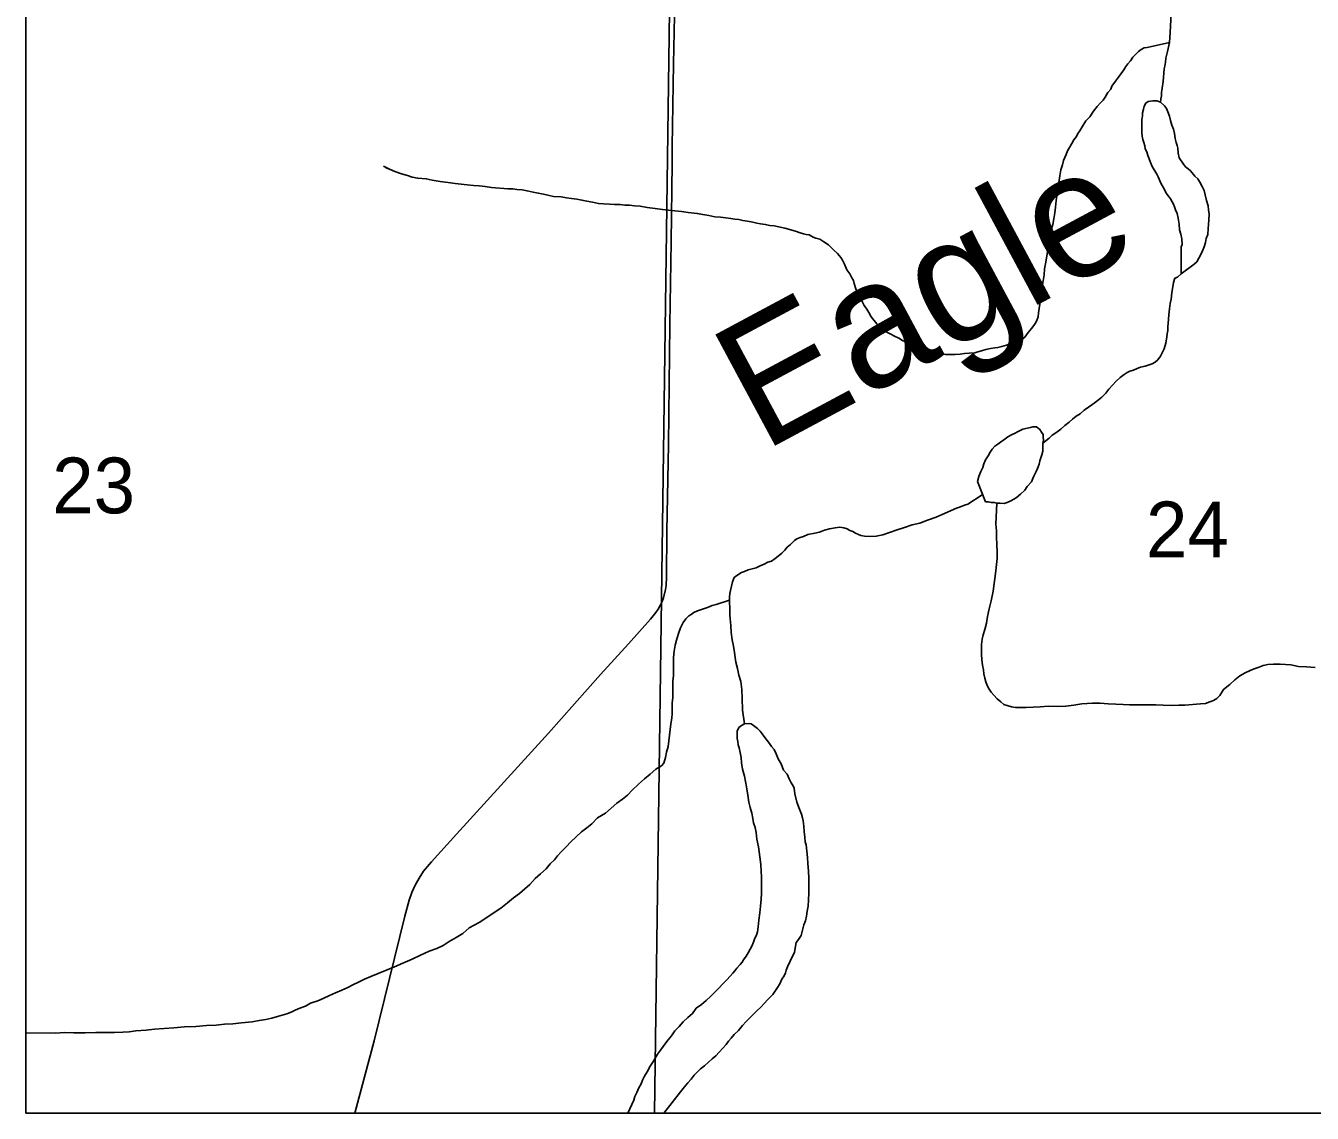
# Model space of a CAD drawing. Extents: x 0 to 68, y 0 to 52.9.
# Drawn here: x 42.258 to 43.278, y 31.143 to 32.005 of the extents above; entities that cross this region are included whole.
import ezdxf

# ---------------------------------------------------------------- set-up
doc = ezdxf.new("R2010")
doc.units = 0
for name, color, linetype in [('Default', 7, 'Continuous'), ('GM_X_Minor_River', 7, 'Continuous'), ('GM_X_Minor_River_Text', 7, 'Continuous'), ('GM_X_Township_Road', 7, 'Continuous')]:
    doc.layers.add(name, color=color, linetype=linetype)

msp = doc.modelspace()

# ---------------------------------------------------------------- linework, layer by layer
at = {"layer": 'Default'}
for q in [(42.2581, 38.5351), (49.6501, 31.1431)]:
    msp.add_line((42.2581, 31.1431), q, dxfattribs=at)
msp.add_lwpolyline([(42.2581, 32.1845), (42.7704, 32.1726), (42.7565, 31.1431)], dxfattribs=at)
at = {"layer": 'GM_X_Minor_River'}
for points in [[(43.1669, 32.0405), (43.1662, 32.0244), (43.1661, 32.0192), (43.1657, 32.0136), (43.1656, 32.0096), (43.1652, 32.0052), (43.1651, 31.9999), (43.1646, 31.9919), (43.163, 31.9847), (43.1617, 31.9795), (43.1613, 31.9763), (43.1608, 31.9731), (43.1604, 31.9711), (43.1595, 31.961), (43.1587, 31.9558), (43.1582, 31.9522), (43.1582, 31.9498), (43.1578, 31.9474), (43.1578, 31.947), (43.1573, 31.9446)], [(42.9282, 31.7746), (42.9325, 31.7689), (42.9365, 31.7648), (42.9405, 31.7624), (42.9437, 31.7607), (42.9465, 31.7591), (42.9501, 31.7575), (42.9529, 31.7558), (42.9553, 31.7546), (42.9581, 31.7526), (42.9617, 31.7505), (42.9653, 31.7493), (42.9677, 31.748), (42.9761, 31.7455), (42.9793, 31.7451), (42.9833, 31.7451), (42.9869, 31.7446), (42.9906, 31.7446), (42.9946, 31.7445), (42.9986, 31.7449), (43.0022, 31.7453), (43.0058, 31.7456), (43.0103, 31.746), (43.0127, 31.7468), (43.0155, 31.7475), (43.0191, 31.7487), (43.0228, 31.7495), (43.026, 31.7498), (43.0284, 31.7502), (43.0316, 31.751), (43.0353, 31.7521), (43.0393, 31.7537), (43.0429, 31.7549), (43.0457, 31.7561), (43.0478, 31.7568), (43.0498, 31.7584), (43.0526, 31.762), (43.0551, 31.7652), (43.0571, 31.7676), (43.0587, 31.77), (43.0596, 31.7724), (43.0604, 31.7744), (43.0608, 31.7776), (43.0617, 31.7844), (43.0626, 31.79), (43.0634, 31.7969), (43.0643, 31.8029), (43.0651, 31.8077), (43.0656, 31.8125), (43.0665, 31.8177), (43.0673, 31.8229), (43.0682, 31.8274), (43.069, 31.8318), (43.0699, 31.8366), (43.0707, 31.8434), (43.072, 31.8478), (43.0728, 31.8522), (43.0737, 31.857), (43.0741, 31.8614), (43.0746, 31.8667), (43.0754, 31.8719), (43.0776, 31.8863), (43.0784, 31.8911), (43.0797, 31.8951), (43.0805, 31.8984), (43.0817, 31.9008), (43.0826, 31.9032), (43.0838, 31.906), (43.0854, 31.9088), (43.0871, 31.9119), (43.0887, 31.9147), (43.0908, 31.9175), (43.092, 31.9199), (43.0936, 31.9219), (43.0952, 31.9251), (43.0981, 31.9299), (43.1014, 31.9331), (43.1042, 31.9375), (43.1071, 31.9411), (43.1095, 31.9439), (43.1119, 31.9462), (43.1136, 31.9486), (43.1156, 31.9522), (43.1181, 31.955), (43.1189, 31.9574), (43.1217, 31.9614), (43.1242, 31.9646), (43.1262, 31.9674), (43.1283, 31.9702), (43.1299, 31.973), (43.1315, 31.975), (43.1335, 31.9774), (43.1356, 31.9802), (43.138, 31.9829), (43.1401, 31.9849), (43.1421, 31.9865), (43.1445, 31.9877), (43.1469, 31.9881), (43.1646, 31.9919)], [(43.1513, 31.9458), (43.1477, 31.9451), (43.1457, 31.9439), (43.1444, 31.9415), (43.144, 31.9391), (43.1432, 31.9363), (43.1432, 31.9339), (43.1427, 31.9307), (43.1427, 31.927), (43.1427, 31.9242), (43.1426, 31.9206), (43.143, 31.9178), (43.1434, 31.915), (43.1442, 31.9126), (43.1449, 31.9101), (43.1453, 31.9077), (43.1465, 31.9053), (43.1473, 31.9025), (43.1485, 31.8997), (43.1496, 31.8968), (43.1508, 31.8936), (43.1544, 31.8875), (43.1556, 31.8855), (43.1563, 31.8835), (43.1575, 31.8811), (43.1587, 31.8786), (43.1607, 31.8754), (43.1619, 31.8726), (43.1638, 31.8702), (43.1654, 31.8681), (43.1666, 31.8657), (43.1678, 31.8637), (43.1686, 31.8617), (43.1694, 31.8592), (43.1705, 31.8564), (43.1713, 31.8528), (43.1721, 31.848), (43.1724, 31.8435), (43.1736, 31.8399), (43.1744, 31.8363), (43.1747, 31.8319), (43.1739, 31.8299), (43.1737, 31.8086)], [(43.1737, 31.8086), (43.1842, 31.8161), (43.1862, 31.8181), (43.1879, 31.8209), (43.1899, 31.8249), (43.1907, 31.8269), (43.192, 31.8301), (43.1932, 31.8333), (43.1937, 31.8365), (43.1949, 31.8397), (43.1953, 31.8445), (43.1954, 31.8477), (43.1958, 31.8513), (43.1959, 31.8558), (43.1955, 31.8594), (43.1951, 31.8626), (43.1939, 31.8666), (43.1928, 31.8711), (43.192, 31.8747), (43.1904, 31.8779), (43.1885, 31.8812), (43.1869, 31.884), (43.1845, 31.886), (43.1813, 31.8901), (43.1793, 31.8917), (43.1773, 31.8933), (43.1757, 31.8954), (43.1722, 31.9006), (43.1714, 31.9042), (43.1711, 31.9083), (43.1707, 31.9103), (43.1699, 31.9127), (43.1691, 31.9159), (43.1684, 31.9199), (43.1676, 31.9232), (43.1664, 31.9264), (43.1652, 31.93), (43.1645, 31.9336), (43.1633, 31.9369), (43.1621, 31.9397), (43.1605, 31.9417), (43.1573, 31.9446), (43.1545, 31.9458), (43.1513, 31.9458)], [(42.5415, 31.8939), (42.5463, 31.8915), (42.5435, 31.8927), (42.5463, 31.8915), (42.5507, 31.8898), (42.5559, 31.8878), (42.5607, 31.8865), (42.5643, 31.8853), (42.5687, 31.8844), (42.5755, 31.8839), (42.5803, 31.8827), (42.5864, 31.8818), (42.5928, 31.8809), (42.5984, 31.8801), (42.6032, 31.8796), (42.608, 31.8792), (42.6129, 31.8787), (42.6173, 31.8783), (42.6221, 31.8778), (42.6273, 31.877), (42.6402, 31.876), (42.6442, 31.876), (42.6474, 31.8755), (42.6514, 31.8751), (42.6554, 31.8743), (42.6602, 31.8734), (42.6642, 31.8726), (42.6683, 31.8717), (42.6719, 31.8709), (42.6763, 31.87), (42.6823, 31.8696), (42.6867, 31.8687), (42.6907, 31.8683), (42.6947, 31.8678), (42.6988, 31.867), (42.7028, 31.8661), (42.7072, 31.8653), (42.712, 31.8644), (42.716, 31.864), (42.7208, 31.8639), (42.7248, 31.8635), (42.7293, 31.8634), (42.7329, 31.863), (42.7365, 31.863), (42.7405, 31.8625), (42.7449, 31.8621), (42.7505, 31.8612), (42.757, 31.8603), (42.7626, 31.8595), (42.7674, 31.859), (42.7726, 31.8586), (42.7779, 31.8581), (42.7831, 31.8573), (42.7903, 31.8564), (42.7947, 31.8555), (42.7995, 31.8547), (42.8043, 31.8538), (42.8088, 31.8534), (42.8128, 31.8529), (42.8168, 31.8525), (42.82, 31.852), (42.8232, 31.8516), (42.8264, 31.8508), (42.83, 31.8503), (42.8344, 31.8495), (42.8376, 31.8486), (42.8405, 31.8482), (42.8441, 31.8478), (42.8477, 31.8469), (42.8513, 31.8465), (42.8597, 31.8448), (42.8625, 31.844), (42.8653, 31.8431), (42.8681, 31.8423), (42.8717, 31.8411), (42.8745, 31.8402), (42.8765, 31.8398), (42.879, 31.8394), (42.8822, 31.8377), (42.8842, 31.8369), (42.8874, 31.8361), (42.8906, 31.834), (42.8942, 31.8316), (42.8965, 31.8295), (42.8989, 31.8271), (42.9013, 31.8247), (42.9041, 31.8214), (42.9053, 31.8194), (42.9069, 31.8162), (42.9088, 31.8117), (42.9112, 31.8085), (42.9128, 31.8053), (42.914, 31.8032), (42.9147, 31.8008), (42.9159, 31.7968), (42.9183, 31.7915), (42.9206, 31.7871), (42.9226, 31.7835), (42.9246, 31.7806), (42.9262, 31.7778), (42.9282, 31.7746)], [(43.1737, 31.8086), (43.1708, 31.8058), (43.1688, 31.805), (43.1676, 31.8018), (43.1663, 31.7934), (43.1658, 31.7886), (43.165, 31.785), (43.1646, 31.7809), (43.1641, 31.7761), (43.1637, 31.7725), (43.1636, 31.7693), (43.1632, 31.7669), (43.1632, 31.7637), (43.1628, 31.7609), (43.1623, 31.7585), (43.1615, 31.7536), (43.1602, 31.7492), (43.1586, 31.746), (43.1574, 31.7432), (43.1553, 31.7404), (43.1533, 31.7385), (43.1509, 31.7373), (43.1484, 31.7365), (43.1452, 31.7353), (43.1416, 31.7346), (43.1388, 31.7334), (43.1359, 31.7322), (43.1331, 31.7314), (43.1311, 31.7303), (43.1287, 31.7287), (43.1254, 31.7263), (43.1222, 31.7235), (43.1193, 31.7203), (43.1165, 31.7171), (43.1141, 31.714), (43.1108, 31.7108), (43.1084, 31.7088), (43.1059, 31.7068), (43.1031, 31.7048), (43.1003, 31.7028), (43.097, 31.7005), (43.0938, 31.6977), (43.0906, 31.6957), (43.0877, 31.6933), (43.0849, 31.6909), (43.0816, 31.6882), (43.0784, 31.6854), (43.0744, 31.6826), (43.0715, 31.6806), (43.0691, 31.6783), (43.0642, 31.6743)], [(43.0643, 31.6791), (43.0643, 31.6811), (43.0631, 31.6831), (43.0619, 31.6852), (43.0591, 31.6872), (43.0563, 31.6872), (43.0543, 31.6868), (43.0483, 31.6853), (43.0442, 31.6833), (43.0422, 31.6822), (43.0394, 31.681), (43.0365, 31.6794), (43.0333, 31.677), (43.0305, 31.675), (43.0284, 31.6735), (43.026, 31.6719), (43.024, 31.6695), (43.0223, 31.6671), (43.0207, 31.6643), (43.0187, 31.6611), (43.0174, 31.6579), (43.0166, 31.6551), (43.015, 31.6519), (43.0133, 31.6479), (43.0125, 31.6439), (43.0187, 31.6277)], [(43.0187, 31.6277), (43.0212, 31.6277), (43.0232, 31.6273), (43.0256, 31.6273), (43.0276, 31.6268), (43.03, 31.6268), (43.0336, 31.6264), (43.036, 31.6272), (43.0389, 31.6287), (43.0429, 31.6311), (43.0465, 31.6339), (43.0498, 31.6371), (43.0518, 31.6399), (43.0551, 31.6438), (43.0563, 31.6462), (43.0571, 31.6482), (43.0588, 31.6518), (43.06, 31.6542), (43.0612, 31.6578), (43.0617, 31.6602), (43.0625, 31.6626), (43.0633, 31.6651), (43.0642, 31.6679), (43.0642, 31.6707), (43.0642, 31.6743), (43.0647, 31.6767), (43.0643, 31.6791)], [(42.8277, 31.4517), (42.8262, 31.4626), (42.8259, 31.4722), (42.8255, 31.4791), (42.8248, 31.4855), (42.8232, 31.4903), (42.8221, 31.4956), (42.8209, 31.5008), (42.8202, 31.5044), (42.8198, 31.5085), (42.819, 31.5133), (42.8179, 31.5185), (42.8171, 31.5242), (42.8168, 31.5298), (42.8164, 31.535), (42.8161, 31.5386), (42.8161, 31.5418), (42.8161, 31.5447), (42.8158, 31.5471), (42.8158, 31.5499), (42.8158, 31.5523), (42.8162, 31.5551), (42.8167, 31.5575), (42.8183, 31.5643), (42.8196, 31.5679), (42.8216, 31.5695), (42.8253, 31.5719), (42.8277, 31.5727), (42.8305, 31.5738), (42.8337, 31.5746), (42.8369, 31.5754), (42.8402, 31.577), (42.8434, 31.5785), (42.8462, 31.5801), (42.8491, 31.5809), (42.8519, 31.5829), (42.8543, 31.5848), (42.8572, 31.5872), (42.8596, 31.5896), (42.8616, 31.592), (42.8641, 31.594), (42.8673, 31.5972), (42.8693, 31.5984), (42.8718, 31.5995), (42.8746, 31.6003), (42.8778, 31.6019), (42.8834, 31.603), (42.8871, 31.6038), (42.8911, 31.6054), (42.8951, 31.6065), (42.8996, 31.6073), (42.9032, 31.6076), (42.9064, 31.6072), (42.9092, 31.6064), (42.9112, 31.6052), (42.9136, 31.6043), (42.9156, 31.6031), (42.918, 31.6019), (42.92, 31.601), (42.9228, 31.6006), (42.9272, 31.6002), (42.9321, 31.6005), (42.9373, 31.6017), (42.9425, 31.6036), (42.9486, 31.6056), (42.9546, 31.6075), (42.9607, 31.6095), (42.9667, 31.611), (42.9728, 31.6134), (42.9796, 31.6157), (42.9845, 31.6177), (42.9958, 31.6228), (42.999, 31.6239), (43.0022, 31.6251), (43.0047, 31.6259), (43.0162, 31.6334)], [(43.0276, 31.6268), (43.0271, 31.6156), (43.027, 31.61), (43.0274, 31.6047), (43.0273, 31.5999), (43.0277, 31.5939), (43.028, 31.5879), (43.0279, 31.583), (43.0275, 31.5782), (43.027, 31.573), (43.0249, 31.5569), (43.0232, 31.5493), (43.0215, 31.5429), (43.0203, 31.5369), (43.0194, 31.5317), (43.0181, 31.5265), (43.0169, 31.5225)], [(42.4685, 31.2232), (42.4717, 31.2248), (42.4754, 31.2263), (42.4798, 31.2279), (42.4838, 31.2303), (42.4895, 31.2322), (42.4939, 31.2342), (42.4988, 31.2365), (42.5036, 31.2385), (42.5085, 31.2408), (42.5133, 31.2428), (42.5173, 31.2448), (42.5218, 31.2471), (42.5266, 31.2495), (42.5315, 31.2515), (42.5504, 31.2593), (42.5569, 31.262), (42.5642, 31.2652), (42.571, 31.2683), (42.5779, 31.2715), (42.5839, 31.2738), (42.5888, 31.2762), (42.5936, 31.2793), (42.5993, 31.2825), (42.6046, 31.2857), (42.6094, 31.29), (42.6175, 31.2944), (42.6236, 31.2983), (42.6292, 31.3023), (42.6345, 31.3058), (42.6398, 31.3098), (42.6446, 31.3138), (42.6495, 31.3173), (42.6535, 31.3209), (42.6576, 31.3245), (42.6617, 31.3293), (42.6661, 31.3328), (42.6706, 31.3368), (42.6738, 31.3408), (42.6771, 31.344), (42.6795, 31.3472), (42.6824, 31.3503), (42.6864, 31.3543), (42.6901, 31.3583), (42.6942, 31.3623), (42.6986, 31.3663), (42.7027, 31.3694), (42.7067, 31.3726), (42.7112, 31.3774), (42.7176, 31.3809), (42.7221, 31.3849), (42.7266, 31.3889), (42.731, 31.392), (42.7351, 31.3952), (42.7387, 31.3992), (42.7436, 31.404), (42.7485, 31.4083), (42.7529, 31.4119), (42.7574, 31.4159), (42.7618, 31.4186), (42.7639, 31.4206), (42.7651, 31.425), (42.766, 31.4294), (42.7672, 31.4339), (42.7694, 31.4519), (42.7702, 31.4563), (42.7703, 31.4599), (42.7703, 31.4636), (42.7704, 31.4684), (42.7708, 31.4724), (42.7709, 31.4772), (42.7709, 31.4812), (42.7709, 31.4857), (42.7714, 31.4901), (42.7714, 31.4949), (42.7715, 31.4997), (42.7715, 31.5045), (42.772, 31.5094), (42.7728, 31.5142), (42.7737, 31.5182), (42.7753, 31.5234), (42.777, 31.5278), (42.779, 31.5322), (42.7811, 31.535), (42.7835, 31.5374), (42.7855, 31.5386), (42.7876, 31.5401), (42.7904, 31.5413), (42.7928, 31.5421), (42.796, 31.5433), (42.7985, 31.544), (42.8021, 31.5456), (42.8053, 31.5464), (42.8158, 31.5499)], [(43.0169, 31.5225), (43.0161, 31.5189), (43.0156, 31.5148), (43.0156, 31.5112), (43.0155, 31.5068), (43.0159, 31.5028), (43.0163, 31.4984), (43.017, 31.4947), (43.0174, 31.4915), (43.0182, 31.4879), (43.0189, 31.4851), (43.0201, 31.4823), (43.0217, 31.4794), (43.0233, 31.477), (43.0253, 31.4746), (43.028, 31.4717), (43.0308, 31.4693), (43.0332, 31.4672), (43.0368, 31.466), (43.0392, 31.4652), (43.0424, 31.4647), (43.0461, 31.4647), (43.0509, 31.4647), (43.0565, 31.465), (43.0621, 31.4653), (43.0686, 31.4657), (43.0754, 31.4656), (43.0823, 31.4659), (43.0887, 31.4667), (43.0951, 31.4678), (43.1036, 31.4681), (43.1096, 31.4681), (43.116, 31.4676), (43.1221, 31.4675), (43.1277, 31.4671), (43.1329, 31.467), (43.1373, 31.467), (43.1426, 31.4669), (43.1482, 31.4669), (43.1538, 31.4668), (43.1594, 31.4667), (43.1667, 31.4663), (43.1719, 31.4666), (43.1767, 31.4666), (43.1892, 31.4676), (43.1932, 31.468), (43.1964, 31.4692), (43.1993, 31.4703), (43.2021, 31.4719), (43.2045, 31.4743), (43.2074, 31.4791), (43.2123, 31.4831), (43.2163, 31.4866), (43.2204, 31.4898), (43.2244, 31.4922), (43.2284, 31.4941), (43.2317, 31.4953), (43.2349, 31.4965), (43.2389, 31.4981), (43.2426, 31.4988), (43.247, 31.4992), (43.2522, 31.4991), (43.2606, 31.4986), (43.2667, 31.4974), (43.2731, 31.4969), (43.2799, 31.4964)], [(42.7639, 31.1431), (42.777, 31.1601), (42.7802, 31.1641), (42.7827, 31.1673), (42.7855, 31.17), (42.7879, 31.1732), (42.7904, 31.176), (42.7928, 31.1784), (42.7961, 31.1808), (42.7993, 31.1836), (42.8021, 31.1863), (42.805, 31.1887), (42.8131, 31.1975), (42.8151, 31.2003), (42.8172, 31.2027), (42.8196, 31.2055), (42.8229, 31.2086), (42.8261, 31.2126), (42.829, 31.2158), (42.8318, 31.2186), (42.8346, 31.2214), (42.8375, 31.2242), (42.8407, 31.2273), (42.846, 31.2329), (42.8501, 31.2373), (42.8533, 31.2421), (42.8558, 31.2457), (42.8574, 31.2493), (42.8591, 31.2521), (42.8603, 31.2545), (42.8607, 31.2565), (42.8619, 31.2593), (42.864, 31.2637), (42.8673, 31.2709), (42.8686, 31.2785), (42.8706, 31.2809), (42.8726, 31.2841), (42.8739, 31.2893), (42.8747, 31.2925), (42.876, 31.2957), (42.8768, 31.2993), (42.8773, 31.3033), (42.8781, 31.3073), (42.8785, 31.3121), (42.8786, 31.3178), (42.8787, 31.323), (42.8787, 31.3294), (42.8784, 31.335), (42.878, 31.3411), (42.8777, 31.3459), (42.8766, 31.356), (42.8758, 31.3584), (42.8754, 31.362), (42.8751, 31.3664), (42.8747, 31.3708), (42.8743, 31.3749), (42.8736, 31.3773), (42.8728, 31.3801), (42.8712, 31.3841), (42.8693, 31.3898), (42.8677, 31.3962), (42.867, 31.4007), (42.8662, 31.4027), (42.8646, 31.4051), (42.863, 31.4083), (42.8615, 31.412), (42.8587, 31.4152), (42.8567, 31.4201), (42.8543, 31.4241), (42.8528, 31.4281), (42.8512, 31.4314), (42.8492, 31.4338), (42.8476, 31.4362), (42.8456, 31.4387), (42.8437, 31.4411), (42.8417, 31.4439), (42.8401, 31.446), (42.8381, 31.448), (42.8349, 31.4504), (42.8329, 31.4517), (42.8305, 31.4521), (42.8277, 31.4517), (42.8253, 31.4505), (42.8232, 31.4489), (42.822, 31.4461), (42.8219, 31.4401), (42.8223, 31.4377), (42.8227, 31.4353), (42.8235, 31.4329)], [(42.8235, 31.4329), (42.8242, 31.4292), (42.825, 31.4252), (42.8254, 31.4208), (42.8261, 31.416), (42.8277, 31.4103), (42.8292, 31.4019), (42.8303, 31.3954), (42.8311, 31.3898), (42.8322, 31.3854), (42.8334, 31.3809), (42.8342, 31.3769), (42.8349, 31.3733), (42.8361, 31.3696), (42.8369, 31.3656), (42.8376, 31.3604), (42.8388, 31.3543), (42.8399, 31.3463), (42.8406, 31.3403), (42.841, 31.335), (42.8413, 31.3302), (42.8413, 31.3262), (42.8413, 31.3218), (42.8412, 31.3173), (42.8408, 31.3129), (42.8403, 31.3073), (42.8399, 31.3021), (42.839, 31.2961), (42.8385, 31.2909), (42.8381, 31.2868), (42.8373, 31.2844), (42.836, 31.282), (42.8348, 31.2788), (42.8336, 31.2756), (42.8323, 31.2732), (42.8307, 31.2704), (42.8291, 31.2676), (42.827, 31.2648), (42.8258, 31.2629), (42.8242, 31.2609), (42.8217, 31.2581), (42.8201, 31.2561), (42.8185, 31.2541), (42.8164, 31.2517), (42.8136, 31.2489), (42.8043, 31.239), (42.801, 31.2358), (42.7974, 31.2326), (42.7937, 31.2294), (42.7893, 31.2263), (42.7864, 31.2223), (42.7828, 31.2191), (42.7791, 31.2155), (42.7759, 31.2119), (42.7726, 31.2084), (42.7698, 31.2044), (42.7673, 31.2012), (42.7653, 31.1988), (42.7632, 31.196), (42.7612, 31.1932), (42.7588, 31.19), (42.7555, 31.1844), (42.753, 31.1804), (42.7506, 31.176), (42.7485, 31.1724), (42.7469, 31.1692), (42.7457, 31.1664), (42.744, 31.1632), (42.7424, 31.1596), (42.7407, 31.1564), (42.7399, 31.1536), (42.7353, 31.1431)], [(42.2581, 31.2069), (42.2818, 31.2066), (42.2887, 31.207), (42.2963, 31.2069), (42.3051, 31.2068), (42.3136, 31.2071), (42.3216, 31.207), (42.3284, 31.207), (42.3349, 31.2073), (42.3401, 31.2076), (42.3453, 31.2084), (42.3534, 31.2091), (42.3602, 31.2098), (42.3679, 31.2102), (42.3755, 31.2109), (42.384, 31.2116), (42.3928, 31.2119), (42.4013, 31.2126), (42.4089, 31.213), (42.4157, 31.2137), (42.4222, 31.214), (42.429, 31.2148), (42.4375, 31.2155), (42.4431, 31.2166), (42.4483, 31.2174), (42.4532, 31.2185), (42.4576, 31.2197), (42.4612, 31.2208), (42.4649, 31.222), (42.4685, 31.2232)]]:
    msp.add_lwpolyline(points, dxfattribs=at)
at = {"layer": 'GM_X_Township_Road'}
msp.add_lwpolyline([(42.5189, 31.1431), (42.5341, 31.2006), (42.5584, 31.2993), (42.5619, 31.3119), (42.5641, 31.318), (42.5667, 31.3239), (42.5698, 31.3296), (42.5734, 31.3349), (42.5796, 31.3425), (42.5995, 31.3643), (42.6238, 31.391), (42.6723, 31.4445), (42.7137, 31.491), (42.7358, 31.5152), (42.7533, 31.5348), (42.7575, 31.54), (42.7593, 31.5428), (42.761, 31.5456), (42.7624, 31.5487), (42.7635, 31.5518), (42.7651, 31.5583), (42.7655, 31.5616), (42.7659, 31.5683), (42.7662, 31.6044), (42.7674, 31.6733), (42.7686, 31.7684), (42.7695, 31.834), (42.7703, 31.8963), (42.7704, 31.9094), (42.7715, 31.975), (42.7735, 32.0767)], dxfattribs=at)

# ---------------------------------------------------------------- texts
at = {"layer": 'Default'}
for s, p in [('23', (42.279, 31.6187)), ('24', (43.1459, 31.5838))]:
    msp.add_text(s, height=0.0442, rotation=0, dxfattribs=at).set_placement(p)
at = {"layer": 'GM_X_Minor_River_Text'}
msp.add_text('Eagle', height=0.10004, rotation=28.2145, dxfattribs=at).set_placement((42.8423, 31.6671))

doc.saveas('drawing.dxf')
